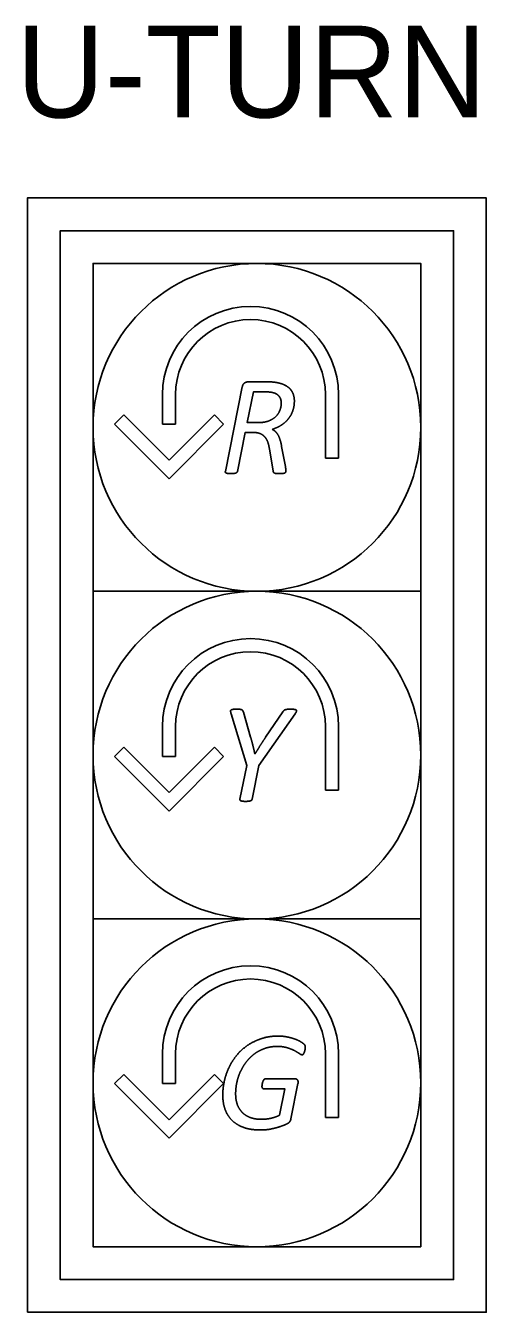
# Model space of a CAD drawing. Extents: x -30.3 to 21.6, y 6.6 to 27.2.
# Drawn here: x 17.123 to 17.826, y 12.676 to 14.638 of the extents above; entities that cross this region are included whole.
import ezdxf

# ---------------------------------------------------------------- set-up
doc = ezdxf.new("R2010")
doc.units = 0
doc.layers.add('UT_X_Water', color=7, linetype='Continuous')
doc.layers.add('VG_X_Cells', color=7, linetype='Continuous')

msp = doc.modelspace()

# ---------------------------------------------------------------- linework, layer by layer
at = {"layer": 'VG_X_Cells'}
for p, q in [((17.4627, 14.095), (17.493, 14.095)), ((17.4627, 14.095), (17.493, 14.095)), ((17.3319, 14.0303), (17.3319, 14.0757)), ((17.3519, 14.0757), (17.3519, 14.0303)), ((17.4278, 13.9583), (17.4537, 14.0875)), ((17.4278, 13.9583), (17.4537, 14.0875)), ((17.5805, 13.9788), (17.5805, 14.0757)), ((17.6005, 14.0757), (17.6005, 13.9788)), ((17.5131, 14.0629), (17.5131, 14.0629)), ((17.2727, 14.0445), (17.2585, 14.0303)), ((17.3419, 13.9753), (17.2727, 14.0445)), ((17.4111, 14.0445), (17.3419, 13.9753)), ((17.4252, 14.0303), (17.4111, 14.0445)), ((17.2585, 14.0303), (17.3419, 13.947)), ((17.3519, 14.0303), (17.3319, 14.0303)), ((17.3419, 13.947), (17.4252, 14.0303)), ((17.5137, 13.9965), (17.5195, 13.9657)), ((17.5137, 13.9965), (17.5195, 13.9657)), ((17.5006, 13.9595), (17.4951, 13.9923)), ((17.5006, 13.9595), (17.4951, 13.9923)), ((17.6005, 13.9788), (17.5805, 13.9788)), ((17.4553, 13.5912), (17.4664, 13.553)), ((17.4553, 13.5912), (17.4664, 13.553)), ((17.4893, 13.5529), (17.5156, 13.5918)), ((17.4893, 13.5529), (17.5156, 13.5918)), ((17.3319, 13.5237), (17.3319, 13.5691)), ((17.3519, 13.5691), (17.3519, 13.5237)), ((17.5805, 13.4722), (17.5805, 13.5691)), ((17.6005, 13.5691), (17.6005, 13.4722)), ((17.2727, 13.5378), (17.2585, 13.5237)), ((17.2585, 13.5237), (17.3419, 13.4403)), ((17.3419, 13.4686), (17.2727, 13.5378)), ((17.3519, 13.5237), (17.3319, 13.5237)), ((17.4111, 13.5378), (17.3419, 13.4686)), ((17.3419, 13.4403), (17.4252, 13.5237)), ((17.4252, 13.5237), (17.4111, 13.5378)), ((17.4728, 13.5273), (17.473, 13.5273)), ((17.4728, 13.5273), (17.473, 13.5273)), ((17.6005, 13.4722), (17.5805, 13.4722)), ((17.3319, 13.0244), (17.3319, 13.0698)), ((17.3519, 13.0698), (17.3519, 13.0244)), ((17.5805, 12.9729), (17.5805, 13.0698)), ((17.6005, 13.0698), (17.6005, 12.9729)), ((17.2727, 13.0386), (17.2585, 13.0244)), ((17.3419, 12.9694), (17.2727, 13.0386)), ((17.4111, 13.0386), (17.3419, 12.9694)), ((17.4252, 13.0244), (17.4111, 13.0386)), ((17.2585, 13.0244), (17.3419, 12.9411)), ((17.3519, 13.0244), (17.3319, 13.0244)), ((17.3419, 12.9411), (17.4252, 13.0244)), ((17.4894, 13.0319), (17.5336, 13.0319)), ((17.4894, 13.0319), (17.5336, 13.0319)), ((17.5386, 13.0244), (17.5279, 12.9707)), ((17.5386, 13.0244), (17.5279, 12.9707)), ((17.6005, 12.9729), (17.5805, 12.9729))]:
    msp.add_line(p, q, dxfattribs=at)
for points in [[(17.1259, 12.6756), (17.8259, 12.6756), (17.8259, 14.3756), (17.1259, 14.3756)], [(17.1759, 14.3256), (17.7759, 14.3256), (17.7759, 12.7256), (17.1759, 12.7256)], [(17.1759, 12.7256), (17.7759, 12.7256), (17.7759, 14.3256), (17.1759, 14.3256)], [(17.2259, 14.2756), (17.7259, 14.2756), (17.7259, 12.7756), (17.2259, 12.7756)], [(17.2259, 13.7756), (17.7259, 13.7756), (17.7259, 14.2756), (17.2259, 14.2756)], [(17.2259, 13.2756), (17.7259, 13.2756), (17.7259, 13.7756), (17.2259, 13.7756)], [(17.2259, 12.7756), (17.7259, 12.7756), (17.7259, 13.2756), (17.2259, 13.2756)]]:
    msp.add_lwpolyline(points, close=True, dxfattribs=at)
for points in [[(17.4899, 14.0797), (17.4707, 14.0797), (17.4613, 14.0328), (17.4776, 14.0328)], [(17.4706, 14.0178), (17.4582, 14.0178), (17.4463, 13.9583)], [(17.4706, 14.0178), (17.4582, 14.0178), (17.4463, 13.9583)], [(17.4501, 13.4583), (17.4604, 13.5098), (17.4366, 13.5884)], [(17.4501, 13.4583), (17.4604, 13.5098), (17.4366, 13.5884)], [(17.5341, 13.5884), (17.4789, 13.5098), (17.4687, 13.4583)], [(17.5341, 13.5884), (17.4789, 13.5098), (17.4687, 13.4583)], [(17.5105, 12.9763), (17.5185, 13.0166), (17.4864, 13.0166)], [(17.5105, 12.9763), (17.5185, 13.0166), (17.4864, 13.0166)]]:
    msp.add_lwpolyline(points, dxfattribs=at)
for centre in [(17.4759, 14.0256), (17.4759, 13.5256), (17.4759, 13.0256)]:
    msp.add_circle(centre, 0.25, dxfattribs=at)
for centre, radius in [((17.4662, 14.0757), 0.1343), ((17.4662, 14.0757), 0.1143), ((17.4662, 13.5691), 0.1343), ((17.4662, 13.5691), 0.1143), ((17.4662, 13.0698), 0.1343), ((17.4662, 13.0698), 0.1143)]:
    msp.add_arc(centre, radius, 0, 180, dxfattribs=at)
for points in [[(17.4537, 14.0875), (17.4545, 14.0916), (17.4571, 14.0933)], [(17.4537, 14.0875), (17.4545, 14.0916), (17.4571, 14.0933)], [(17.4571, 14.0933), (17.4596, 14.095), (17.4627, 14.095)], [(17.4571, 14.0933), (17.4596, 14.095), (17.4627, 14.095)], [(17.493, 14.095), (17.5029, 14.095), (17.5104, 14.093)], [(17.493, 14.095), (17.5029, 14.095), (17.5104, 14.093)], [(17.5104, 14.093), (17.5179, 14.0911), (17.5229, 14.0874)], [(17.5104, 14.093), (17.5179, 14.0911), (17.5229, 14.0874)], [(17.5005, 14.0786), (17.4961, 14.0797), (17.4899, 14.0797)], [(17.5078, 14.0751), (17.505, 14.0774), (17.5005, 14.0786)], [(17.5118, 14.0697), (17.5105, 14.0728), (17.5078, 14.0751)], [(17.5229, 14.0874), (17.528, 14.0837), (17.5305, 14.0783)], [(17.5229, 14.0874), (17.528, 14.0837), (17.5305, 14.0783)], [(17.5305, 14.0783), (17.5331, 14.0728), (17.5331, 14.0658)], [(17.5305, 14.0783), (17.5331, 14.0728), (17.5331, 14.0658)], [(17.5111, 14.0519), (17.5131, 14.0572), (17.5131, 14.0629)], [(17.5131, 14.0629), (17.5131, 14.0666), (17.5118, 14.0697)], [(17.5331, 14.0658), (17.5331, 14.0584), (17.531, 14.0517)], [(17.5331, 14.0658), (17.5331, 14.0584), (17.531, 14.0517)], [(17.4776, 14.0328), (17.4872, 14.0328), (17.4939, 14.0354)], [(17.4939, 14.0354), (17.5006, 14.038), (17.5049, 14.0422)], [(17.5049, 14.0422), (17.5091, 14.0465), (17.5111, 14.0519)], [(17.5246, 14.0395), (17.5204, 14.0339), (17.514, 14.0295)], [(17.5246, 14.0395), (17.5204, 14.0339), (17.514, 14.0295)], [(17.531, 14.0517), (17.5289, 14.0451), (17.5246, 14.0395)], [(17.531, 14.0517), (17.5289, 14.0451), (17.5246, 14.0395)], [(17.4812, 14.0159), (17.4768, 14.0178), (17.4706, 14.0178)], [(17.4812, 14.0159), (17.4768, 14.0178), (17.4706, 14.0178)], [(17.4883, 14.0107), (17.4855, 14.014), (17.4812, 14.0159)], [(17.4883, 14.0107), (17.4855, 14.014), (17.4812, 14.0159)], [(17.514, 14.0295), (17.5075, 14.0251), (17.499, 14.0225)], [(17.514, 14.0295), (17.5075, 14.0251), (17.499, 14.0225)], [(17.499, 14.0225), (17.5047, 14.0204), (17.5083, 14.0138)], [(17.499, 14.0225), (17.5047, 14.0204), (17.5083, 14.0138)], [(17.5083, 14.0138), (17.5118, 14.0073), (17.5137, 13.9965)], [(17.5083, 14.0138), (17.5118, 14.0073), (17.5137, 13.9965)], [(17.4927, 14.0026), (17.4911, 14.0073), (17.4883, 14.0107)], [(17.4927, 14.0026), (17.4911, 14.0073), (17.4883, 14.0107)], [(17.4951, 13.9923), (17.4943, 13.998), (17.4927, 14.0026)], [(17.4951, 13.9923), (17.4943, 13.998), (17.4927, 14.0026)], [(17.4279, 13.9568), (17.4276, 13.9575), (17.4278, 13.9583)], [(17.4279, 13.9568), (17.4276, 13.9575), (17.4278, 13.9583)], [(17.4293, 13.9558), (17.4283, 13.9562), (17.4279, 13.9568)], [(17.4293, 13.9558), (17.4283, 13.9562), (17.4279, 13.9568)], [(17.432, 13.9552), (17.4302, 13.9554), (17.4293, 13.9558)], [(17.432, 13.9552), (17.4302, 13.9554), (17.4293, 13.9558)], [(17.4363, 13.955), (17.4338, 13.955), (17.432, 13.9552)], [(17.4363, 13.955), (17.4338, 13.955), (17.432, 13.9552)], [(17.4408, 13.9553), (17.439, 13.955), (17.4363, 13.955)], [(17.4408, 13.9553), (17.439, 13.955), (17.4363, 13.955)], [(17.4438, 13.9559), (17.4426, 13.9555), (17.4408, 13.9553)], [(17.4438, 13.9559), (17.4426, 13.9555), (17.4408, 13.9553)], [(17.4455, 13.9569), (17.445, 13.9563), (17.4438, 13.9559)], [(17.4455, 13.9569), (17.445, 13.9563), (17.4438, 13.9559)], [(17.4463, 13.9583), (17.4461, 13.9576), (17.4455, 13.9569)], [(17.4463, 13.9583), (17.4461, 13.9576), (17.4455, 13.9569)], [(17.5012, 13.9573), (17.5008, 13.9581), (17.5006, 13.9595)], [(17.5012, 13.9573), (17.5008, 13.9581), (17.5006, 13.9595)], [(17.5025, 13.956), (17.5016, 13.9565), (17.5012, 13.9573)], [(17.5025, 13.956), (17.5016, 13.9565), (17.5012, 13.9573)], [(17.5052, 13.9552), (17.5034, 13.9554), (17.5025, 13.956)], [(17.5052, 13.9552), (17.5034, 13.9554), (17.5025, 13.956)], [(17.5097, 13.955), (17.5069, 13.955), (17.5052, 13.9552)], [(17.5097, 13.955), (17.5069, 13.955), (17.5052, 13.9552)], [(17.5148, 13.9552), (17.5127, 13.955), (17.5097, 13.955)], [(17.5148, 13.9552), (17.5127, 13.955), (17.5097, 13.955)], [(17.5181, 13.9558), (17.5169, 13.9554), (17.5148, 13.9552)], [(17.5181, 13.9558), (17.5169, 13.9554), (17.5148, 13.9552)], [(17.5198, 13.957), (17.5192, 13.9563), (17.5181, 13.9558)], [(17.5198, 13.957), (17.5192, 13.9563), (17.5181, 13.9558)], [(17.5195, 13.9657), (17.5198, 13.9636), (17.5201, 13.9618)], [(17.5195, 13.9657), (17.5198, 13.9636), (17.5201, 13.9618)], [(17.5203, 13.9586), (17.5203, 13.9577), (17.5198, 13.957)], [(17.5203, 13.9586), (17.5203, 13.9577), (17.5198, 13.957)], [(17.5201, 13.9618), (17.5203, 13.96), (17.5203, 13.9586)], [(17.5201, 13.9618), (17.5203, 13.96), (17.5203, 13.9586)], [(17.4358, 13.5922), (17.4357, 13.5936), (17.4365, 13.5944)], [(17.4358, 13.5922), (17.4357, 13.5936), (17.4365, 13.5944)], [(17.4366, 13.5884), (17.436, 13.5908), (17.4358, 13.5922)], [(17.4366, 13.5884), (17.436, 13.5908), (17.4358, 13.5922)], [(17.4365, 13.5944), (17.4374, 13.5951), (17.4394, 13.5954)], [(17.4365, 13.5944), (17.4374, 13.5951), (17.4394, 13.5954)], [(17.4394, 13.5954), (17.4414, 13.5956), (17.4451, 13.5956)], [(17.4394, 13.5954), (17.4414, 13.5956), (17.4451, 13.5956)], [(17.4451, 13.5956), (17.4481, 13.5956), (17.4499, 13.5955)], [(17.4451, 13.5956), (17.4481, 13.5956), (17.4499, 13.5955)], [(17.4499, 13.5955), (17.4517, 13.5953), (17.4528, 13.5948)], [(17.4499, 13.5955), (17.4517, 13.5953), (17.4528, 13.5948)], [(17.4528, 13.5948), (17.4539, 13.5942), (17.4544, 13.5934)], [(17.4528, 13.5948), (17.4539, 13.5942), (17.4544, 13.5934)], [(17.4544, 13.5934), (17.4549, 13.5926), (17.4553, 13.5912)], [(17.4544, 13.5934), (17.4549, 13.5926), (17.4553, 13.5912)], [(17.5156, 13.5918), (17.5163, 13.5928), (17.5171, 13.5936)], [(17.5156, 13.5918), (17.5163, 13.5928), (17.5171, 13.5936)], [(17.5171, 13.5936), (17.5179, 13.5944), (17.5192, 13.5948)], [(17.5171, 13.5936), (17.5179, 13.5944), (17.5192, 13.5948)], [(17.5192, 13.5948), (17.5205, 13.5953), (17.5224, 13.5955)], [(17.5192, 13.5948), (17.5205, 13.5953), (17.5224, 13.5955)], [(17.5224, 13.5955), (17.5243, 13.5956), (17.5275, 13.5956)], [(17.5224, 13.5955), (17.5243, 13.5956), (17.5275, 13.5956)], [(17.5275, 13.5956), (17.5314, 13.5956), (17.5335, 13.5953)], [(17.5275, 13.5956), (17.5314, 13.5956), (17.5335, 13.5953)], [(17.5335, 13.5953), (17.5356, 13.5949), (17.5362, 13.594)], [(17.5335, 13.5953), (17.5356, 13.5949), (17.5362, 13.594)], [(17.5361, 13.5918), (17.5355, 13.5904), (17.5341, 13.5884)], [(17.5361, 13.5918), (17.5355, 13.5904), (17.5341, 13.5884)], [(17.5362, 13.594), (17.5367, 13.5932), (17.5361, 13.5918)], [(17.5362, 13.594), (17.5367, 13.5932), (17.5361, 13.5918)], [(17.4664, 13.553), (17.4684, 13.5463), (17.4699, 13.5401)], [(17.4664, 13.553), (17.4684, 13.5463), (17.4699, 13.5401)], [(17.4809, 13.5401), (17.4848, 13.5464), (17.4893, 13.5529)], [(17.4809, 13.5401), (17.4848, 13.5464), (17.4893, 13.5529)], [(17.4699, 13.5401), (17.4714, 13.5339), (17.4728, 13.5273)], [(17.4699, 13.5401), (17.4714, 13.5339), (17.4728, 13.5273)], [(17.473, 13.5273), (17.4769, 13.5337), (17.4809, 13.5401)], [(17.473, 13.5273), (17.4769, 13.5337), (17.4809, 13.5401)], [(17.4503, 13.4569), (17.4499, 13.4576), (17.4501, 13.4583)], [(17.4503, 13.4569), (17.4499, 13.4576), (17.4501, 13.4583)], [(17.4515, 13.4559), (17.4506, 13.4563), (17.4503, 13.4569)], [(17.4515, 13.4559), (17.4506, 13.4563), (17.4503, 13.4569)], [(17.4542, 13.4553), (17.4525, 13.4555), (17.4515, 13.4559)], [(17.4542, 13.4553), (17.4525, 13.4555), (17.4515, 13.4559)], [(17.4586, 13.455), (17.4559, 13.455), (17.4542, 13.4553)], [(17.4586, 13.455), (17.4559, 13.455), (17.4542, 13.4553)], [(17.463, 13.4553), (17.4612, 13.455), (17.4586, 13.455)], [(17.463, 13.4553), (17.4612, 13.455), (17.4586, 13.455)], [(17.4661, 13.4559), (17.4649, 13.4555), (17.463, 13.4553)], [(17.4661, 13.4559), (17.4649, 13.4555), (17.463, 13.4553)], [(17.4679, 13.4569), (17.4673, 13.4563), (17.4661, 13.4559)], [(17.4679, 13.4569), (17.4673, 13.4563), (17.4661, 13.4559)], [(17.4687, 13.4583), (17.4685, 13.4576), (17.4679, 13.4569)], [(17.4687, 13.4583), (17.4685, 13.4576), (17.4679, 13.4569)], [(17.463, 13.0837), (17.4725, 13.0898), (17.4838, 13.0934)], [(17.463, 13.0837), (17.4725, 13.0898), (17.4838, 13.0934)], [(17.4838, 13.0934), (17.4951, 13.097), (17.5082, 13.097)], [(17.4838, 13.0934), (17.4951, 13.097), (17.5082, 13.097)], [(17.5082, 13.097), (17.5158, 13.097), (17.5223, 13.0956)], [(17.5082, 13.097), (17.5158, 13.097), (17.5223, 13.0956)], [(17.5223, 13.0956), (17.5289, 13.0943), (17.5341, 13.0924)], [(17.5223, 13.0956), (17.5289, 13.0943), (17.5341, 13.0924)], [(17.5341, 13.0924), (17.5392, 13.0905), (17.5428, 13.0883)], [(17.5341, 13.0924), (17.5392, 13.0905), (17.5428, 13.0883)], [(17.4463, 13.0691), (17.4536, 13.0776), (17.463, 13.0837)], [(17.4463, 13.0691), (17.4536, 13.0776), (17.463, 13.0837)], [(17.4885, 13.0783), (17.4801, 13.0755), (17.4731, 13.0705)], [(17.4885, 13.0783), (17.4801, 13.0755), (17.4731, 13.0705)], [(17.5064, 13.0812), (17.4968, 13.0812), (17.4885, 13.0783)], [(17.5064, 13.0812), (17.4968, 13.0812), (17.4885, 13.0783)], [(17.5221, 13.0792), (17.5156, 13.0812), (17.5064, 13.0812)], [(17.5221, 13.0792), (17.5156, 13.0812), (17.5064, 13.0812)], [(17.5333, 13.0748), (17.5287, 13.0772), (17.5221, 13.0792)], [(17.5333, 13.0748), (17.5287, 13.0772), (17.5221, 13.0792)], [(17.5406, 13.0704), (17.5378, 13.0723), (17.5333, 13.0748)], [(17.5406, 13.0704), (17.5378, 13.0723), (17.5333, 13.0748)], [(17.5428, 13.0883), (17.5464, 13.086), (17.5476, 13.0848)], [(17.5428, 13.0883), (17.5464, 13.086), (17.5476, 13.0848)], [(17.5485, 13.073), (17.5481, 13.0717), (17.5475, 13.0706)], [(17.5485, 13.073), (17.5481, 13.0717), (17.5475, 13.0706)], [(17.5476, 13.0848), (17.5489, 13.0836), (17.5494, 13.0826)], [(17.5476, 13.0848), (17.5489, 13.0836), (17.5494, 13.0826)], [(17.5492, 13.0756), (17.5489, 13.0743), (17.5485, 13.073)], [(17.5492, 13.0756), (17.5489, 13.0743), (17.5485, 13.073)], [(17.5496, 13.0779), (17.5495, 13.0768), (17.5492, 13.0756)], [(17.5496, 13.0779), (17.5495, 13.0768), (17.5492, 13.0756)], [(17.5494, 13.0826), (17.5498, 13.0815), (17.5498, 13.0799)], [(17.5494, 13.0826), (17.5498, 13.0815), (17.5498, 13.0799)], [(17.5498, 13.0799), (17.5498, 13.0791), (17.5496, 13.0779)], [(17.5498, 13.0799), (17.5498, 13.0791), (17.5496, 13.0779)], [(17.4341, 13.0505), (17.4391, 13.0605), (17.4463, 13.0691)], [(17.4341, 13.0505), (17.4391, 13.0605), (17.4463, 13.0691)], [(17.4606, 13.0586), (17.4551, 13.0518), (17.4513, 13.0437)], [(17.4606, 13.0586), (17.4551, 13.0518), (17.4513, 13.0437)], [(17.4731, 13.0705), (17.4661, 13.0654), (17.4606, 13.0586)], [(17.4731, 13.0705), (17.4661, 13.0654), (17.4606, 13.0586)], [(17.545, 13.0684), (17.5433, 13.0684), (17.5406, 13.0704)], [(17.545, 13.0684), (17.5433, 13.0684), (17.5406, 13.0704)], [(17.5464, 13.069), (17.5457, 13.0684), (17.545, 13.0684)], [(17.5464, 13.069), (17.5457, 13.0684), (17.545, 13.0684)], [(17.5475, 13.0706), (17.547, 13.0696), (17.5464, 13.069)], [(17.5475, 13.0706), (17.547, 13.0696), (17.5464, 13.069)], [(17.4265, 13.0294), (17.4291, 13.0405), (17.4341, 13.0505)], [(17.4265, 13.0294), (17.4291, 13.0405), (17.4341, 13.0505)], [(17.4513, 13.0437), (17.4474, 13.0357), (17.4455, 13.0269)], [(17.4513, 13.0437), (17.4474, 13.0357), (17.4455, 13.0269)], [(17.4239, 13.0067), (17.4239, 13.0182), (17.4265, 13.0294)], [(17.4239, 13.0067), (17.4239, 13.0182), (17.4265, 13.0294)], [(17.4455, 13.0269), (17.4435, 13.018), (17.4435, 13.009)], [(17.4455, 13.0269), (17.4435, 13.018), (17.4435, 13.009)], [(17.4837, 13.0202), (17.4837, 13.021), (17.4838, 13.0222)], [(17.4837, 13.0202), (17.4837, 13.021), (17.4838, 13.0222)], [(17.4844, 13.0176), (17.4837, 13.0185), (17.4837, 13.0202)], [(17.4844, 13.0176), (17.4837, 13.0185), (17.4837, 13.0202)], [(17.4838, 13.0222), (17.484, 13.0235), (17.4843, 13.0247)], [(17.4838, 13.0222), (17.484, 13.0235), (17.4843, 13.0247)], [(17.4843, 13.0247), (17.4845, 13.026), (17.485, 13.0273)], [(17.4843, 13.0247), (17.4845, 13.026), (17.485, 13.0273)], [(17.4864, 13.0166), (17.4851, 13.0166), (17.4844, 13.0176)], [(17.4864, 13.0166), (17.4851, 13.0166), (17.4844, 13.0176)], [(17.485, 13.0273), (17.4855, 13.0286), (17.4861, 13.0297)], [(17.485, 13.0273), (17.4855, 13.0286), (17.4861, 13.0297)], [(17.4861, 13.0297), (17.4868, 13.0307), (17.4876, 13.0313)], [(17.4861, 13.0297), (17.4868, 13.0307), (17.4876, 13.0313)], [(17.4876, 13.0313), (17.4884, 13.0319), (17.4894, 13.0319)], [(17.4876, 13.0313), (17.4884, 13.0319), (17.4894, 13.0319)], [(17.5336, 13.0319), (17.5366, 13.0319), (17.538, 13.0298)], [(17.5336, 13.0319), (17.5366, 13.0319), (17.538, 13.0298)], [(17.538, 13.0298), (17.5393, 13.0278), (17.5386, 13.0244)], [(17.538, 13.0298), (17.5393, 13.0278), (17.5386, 13.0244)], [(17.4276, 12.9845), (17.4239, 12.9943), (17.4239, 13.0067)], [(17.4276, 12.9845), (17.4239, 12.9943), (17.4239, 13.0067)], [(17.4435, 13.009), (17.4435, 12.9995), (17.4462, 12.9922)], [(17.4435, 13.009), (17.4435, 12.9995), (17.4462, 12.9922)], [(17.4386, 12.9678), (17.4314, 12.9747), (17.4276, 12.9845)], [(17.4386, 12.9678), (17.4314, 12.9747), (17.4276, 12.9845)], [(17.4462, 12.9922), (17.449, 12.985), (17.4541, 12.98)], [(17.4462, 12.9922), (17.449, 12.985), (17.4541, 12.98)], [(17.4541, 12.98), (17.4593, 12.975), (17.4666, 12.9725)], [(17.4541, 12.98), (17.4593, 12.975), (17.4666, 12.9725)], [(17.497, 12.9715), (17.5042, 12.9731), (17.5105, 12.9763)], [(17.497, 12.9715), (17.5042, 12.9731), (17.5105, 12.9763)], [(17.4565, 12.9573), (17.4458, 12.9609), (17.4386, 12.9678)], [(17.4565, 12.9573), (17.4458, 12.9609), (17.4386, 12.9678)], [(17.4812, 12.9537), (17.4672, 12.9537), (17.4565, 12.9573)], [(17.4812, 12.9537), (17.4672, 12.9537), (17.4565, 12.9573)], [(17.4666, 12.9725), (17.474, 12.97), (17.483, 12.97)], [(17.4666, 12.9725), (17.474, 12.97), (17.483, 12.97)], [(17.4969, 12.9551), (17.4894, 12.9537), (17.4812, 12.9537)], [(17.4969, 12.9551), (17.4894, 12.9537), (17.4812, 12.9537)], [(17.483, 12.97), (17.4897, 12.97), (17.497, 12.9715)], [(17.483, 12.97), (17.4897, 12.97), (17.497, 12.9715)], [(17.5103, 12.9585), (17.5044, 12.9566), (17.4969, 12.9551)], [(17.5103, 12.9585), (17.5044, 12.9566), (17.4969, 12.9551)], [(17.5203, 12.9623), (17.5163, 12.9605), (17.5103, 12.9585)], [(17.5203, 12.9623), (17.5163, 12.9605), (17.5103, 12.9585)], [(17.5252, 12.9652), (17.5242, 12.9642), (17.5203, 12.9623)], [(17.5252, 12.9652), (17.5242, 12.9642), (17.5203, 12.9623)], [(17.5267, 12.9674), (17.526, 12.9662), (17.5252, 12.9652)], [(17.5267, 12.9674), (17.526, 12.9662), (17.5252, 12.9652)], [(17.5279, 12.9707), (17.5274, 12.9686), (17.5267, 12.9674)], [(17.5279, 12.9707), (17.5274, 12.9686), (17.5267, 12.9674)]]:
    msp.add_open_spline(points, degree=2, dxfattribs=at)

# ---------------------------------------------------------------- texts
at = {"layer": 'UT_X_Water'}
msp.add_text('U-TURN', height=0.14, dxfattribs=at).set_placement((17.1088, 14.4983))

doc.saveas('drawing.dxf')
